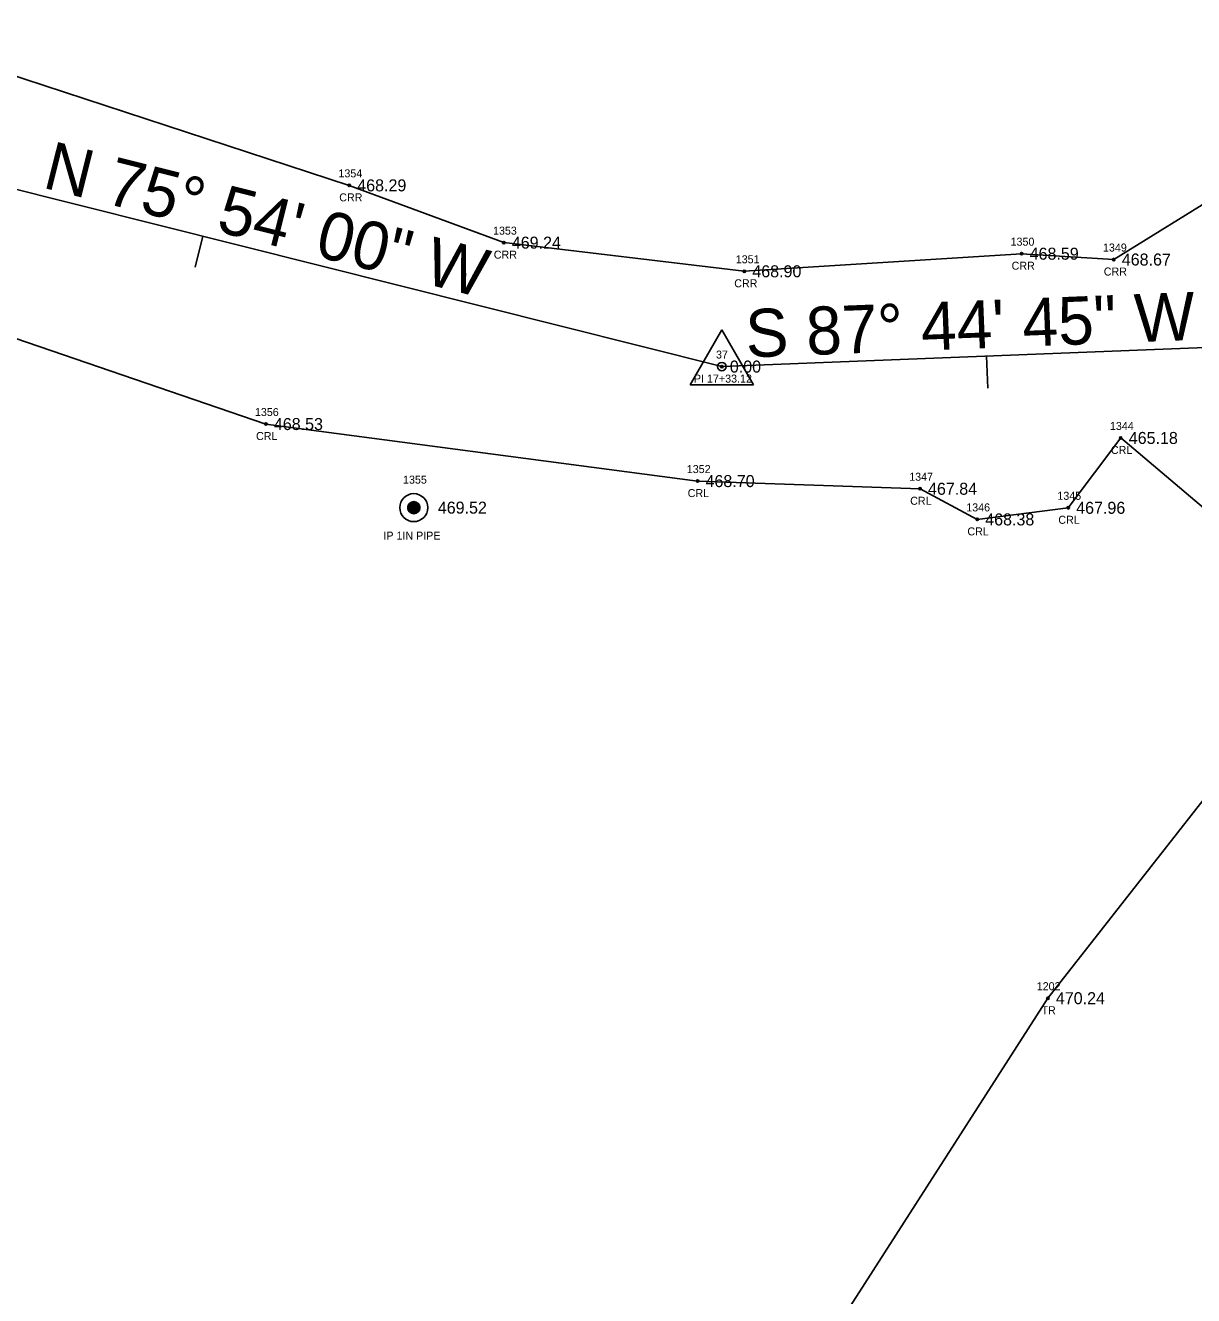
# Model space of a CAD drawing. Extents: x 1740701 to 1743138, y 748181 to 751839.
# Drawn here: x 1741406.9 to 1741552.9, y 750033.3 to 750192 of the extents above; entities that cross this region are included whole.
import ezdxf

# ---------------------------------------------------------------- set-up
doc = ezdxf.new("R2010")
doc.units = 0
for name, color, linetype in [('RD_EX_DV_Prop_txCode', 7, 'Continuous'), ('RD_EX_DV_PropPin', 7, 'Continuous'), ('RD_EX_H2O', 7, 'Continuous'), ('RD_EX_H2O_txCode', 7, 'Continuous'), ('RD_EX_TX_DV_Prop_ELEV', 7, 'Continuous'), ('RD_EX_TX_H2O_ELEV', 7, 'Continuous'), ('RD_EX_TX_VEG_ELEV', 7, 'Continuous'), ('RD_EX_VEG', 7, 'Continuous'), ('RD_EX_VEG_txCode', 7, 'Continuous'), ('RD_HC_Cl', 7, 'Continuous'), ('RD_HC_Data', 7, 'Continuous'), ('RD_HC_Data_Tic', 7, 'Continuous'), ('RD_HC_Survey_ELEV', 7, 'Continuous'), ('RD_HC_txCode', 7, 'Continuous'), ('RD_SMD_Locator', 7, 'Continuous')]:
    doc.layers.add(name, color=color, linetype=linetype)

msp = doc.modelspace()

# ---------------------------------------------------------------- linework, layer by layer
at = {"layer": 'RD_EX_DV_PropPin'}
for p, q in [((1741454.8, 750131.31), (1741454.8, 750132.17)), ((1741454.84, 750131.27), (1741454.84, 750132.21)), ((1741454.87, 750131.23), (1741454.87, 750132.26)), ((1741454.91, 750131.19), (1741454.91, 750132.29)), ((1741454.94, 750131.16), (1741454.94, 750132.32)), ((1741454.98, 750131.13), (1741454.98, 750132.35)), ((1741455.01, 750131.11), (1741455.01, 750132.38)), ((1741455.05, 750131.08), (1741455.05, 750132.4)), ((1741455.08, 750131.07), (1741455.08, 750132.42)), ((1741455.12, 750131.05), (1741455.12, 750132.43)), ((1741455.15, 750131.03), (1741455.15, 750132.45)), ((1741455.19, 750131.02), (1741455.19, 750132.46)), ((1741455.22, 750131.01), (1741455.22, 750132.47)), ((1741455.26, 750131), (1741455.26, 750132.48)), ((1741455.29, 750130.99), (1741455.29, 750132.49)), ((1741455.33, 750130.99), (1741455.33, 750132.49)), ((1741455.36, 750130.98), (1741455.36, 750132.5)), ((1741455.4, 750130.98), (1741455.4, 750132.5)), ((1741455.43, 750130.98), (1741455.43, 750132.5)), ((1741455.47, 750130.98), (1741455.47, 750132.5)), ((1741455.5, 750130.98), (1741455.5, 750132.5)), ((1741455.54, 750130.99), (1741455.54, 750132.49)), ((1741455.57, 750130.99), (1741455.57, 750132.49)), ((1741455.61, 750131), (1741455.61, 750132.48)), ((1741455.64, 750131.01), (1741455.64, 750132.47)), ((1741455.68, 750131.02), (1741455.68, 750132.46)), ((1741455.71, 750131.03), (1741455.71, 750132.45)), ((1741455.75, 750131.05), (1741455.75, 750132.43)), ((1741455.78, 750131.07), (1741455.78, 750132.42)), ((1741455.82, 750131.08), (1741455.82, 750132.4)), ((1741455.85, 750131.11), (1741455.85, 750132.38)), ((1741455.89, 750131.13), (1741455.89, 750132.35)), ((1741455.92, 750131.16), (1741455.92, 750132.32)), ((1741455.96, 750131.19), (1741455.96, 750132.29)), ((1741455.99, 750131.23), (1741455.99, 750132.26)), ((1741456.03, 750131.27), (1741456.03, 750132.21)), ((1741456.06, 750131.31), (1741456.06, 750132.17)), ((1741454.7, 750131.54), (1741454.7, 750131.94)), ((1741454.73, 750131.44), (1741454.73, 750132.04)), ((1741454.77, 750131.37), (1741454.77, 750132.11)), ((1741456.1, 750131.37), (1741456.1, 750132.11)), ((1741456.13, 750131.44), (1741456.13, 750132.04)), ((1741456.17, 750131.54), (1741456.17, 750131.94))]:
    msp.add_line(p, q, dxfattribs=at)
for radius in [1.75, 0.761]:
    msp.add_circle((1741455.43, 750131.74), radius, dxfattribs=at)
at = {"layer": 'RD_EX_H2O'}
for points in [[(1741586.49, 750141.56), (1741579.42, 750140.28), (1741574, 750158.88), (1741556.82, 750171.34), (1741542.92, 750162.75), (1741531.4, 750163.48), (1741496.74, 750161.28), (1741466.68, 750164.86), (1741447.36, 750172.02), (1741386.3, 750192.01)], [(1741577.19, 750059.87), (1741574.31, 750069.19), (1741563.25, 750082.19), (1741560.12, 750095.32), (1741559.96, 750109.5), (1741556.5, 750127.16), (1741554.14, 750131.7), (1741543.79, 750140.45), (1741537.22, 750131.72), (1741525.85, 750130.27), (1741518.7, 750134.1), (1741490.89, 750135.06), (1741436.94, 750142.19), (1741375.71, 750163.12), (1741339.37, 750188.79), (1741331.64, 750190.2), (1741328.64, 750186.11), (1741320.24, 750158.32), (1741318.27, 750146.83), (1741309.48, 750135.97), (1741304.66, 750127.91)]]:
    msp.add_lwpolyline(points, dxfattribs=at)
at = {"layer": 'RD_EX_VEG'}
msp.add_lwpolyline([(1741604.33, 750163.58), (1741599.49, 750153.1), (1741534.68, 750070.43), (1741507.94, 750028.75), (1741481.7, 749984.37), (1741451.24, 749945.89), (1741428.74, 749900.3), (1741397.03, 749864.21), (1741369.46, 749820.4), (1741343.59, 749775.26), (1741290.16, 749691.55)], dxfattribs=at)
at = {"layer": 'RD_HC_Cl'}
for p, q in [((1741493.93, 750149.37), (1741380.2, 750177.94)), ((1741557.27, 750151.87), (1741493.93, 750149.37))]:
    msp.add_line(p, q, dxfattribs=at)
msp.add_arc((1743076.32, 748855.91), 1908.9, 137.32219, 146.96645, dxfattribs=at)
at = {"layer": 'RD_HC_Data'}
for p, q in [((1741489.96, 750147.08), (1741493.93, 750153.96)), ((1741493.93, 750153.96), (1741497.9, 750147.08)), ((1741489.96, 750147.08), (1741497.9, 750147.08))]:
    msp.add_line(p, q, dxfattribs=at)
msp.add_circle((1741493.93, 750149.37), 0.529, dxfattribs=at)
at = {"layer": 'RD_HC_Data_Tic'}
for p, q in [((1741429.06, 750165.67), (1741428.09, 750161.79)), ((1741527.02, 750150.68), (1741527.18, 750146.68))]:
    msp.add_line(p, q, dxfattribs=at)
at = {"layer": 'RD_SMD_Locator'}
for centre in [(1741447.36, 750172.02), (1741466.68, 750164.86), (1741531.4, 750163.48), (1741542.92, 750162.75), (1741496.74, 750161.28), (1741493.93, 750149.37), (1741436.94, 750142.19), (1741543.79, 750140.45), (1741490.89, 750135.06), (1741518.7, 750134.1), (1741455.43, 750131.74), (1741537.22, 750131.72), (1741525.85, 750130.27), (1741534.68, 750070.43)]:
    msp.add_circle(centre, 0.15, dxfattribs=at)

# ---------------------------------------------------------------- texts
at = {"layer": 'RD_EX_DV_Prop_txCode'}
for s, p in [('1355', (1741454.08, 750134.74)), ('IP 1IN PIPE', (1741451.63, 750127.74))]:
    msp.add_text(s, height=1, dxfattribs=at).set_placement(p)
at = {"layer": 'RD_EX_H2O_txCode'}
for s, p in [('1354', (1741446.01, 750173.02)), ('CRR', (1741446.11, 750170.02)), ('1353', (1741465.33, 750165.86)), ('1350', (1741530.02, 750164.48)), ('1349', (1741541.57, 750163.75)), ('CRR', (1741465.43, 750162.86)), ('1351', (1741495.67, 750162.28)), ('CRR', (1741530.15, 750161.48)), ('CRR', (1741541.67, 750160.75)), ('CRR', (1741495.48, 750159.28)), ('1356', (1741435.57, 750143.19)), ('1344', (1741542.44, 750141.45)), ('CRL', (1741435.71, 750140.19)), ('CRL', (1741542.56, 750138.45)), ('1352', (1741489.55, 750136.06)), ('1347', (1741517.35, 750135.1)), ('CRL', (1741489.66, 750133.06)), ('CRL', (1741517.47, 750132.1)), ('1346', (1741524.48, 750131.27)), ('1345', (1741535.87, 750132.72)), ('CRL', (1741535.99, 750129.72)), ('CRL', (1741524.62, 750128.27))]:
    msp.add_text(s, height=1, dxfattribs=at).set_placement(p)
at = {"layer": 'RD_EX_TX_DV_Prop_ELEV'}
msp.add_text('469.52', height=1.5, dxfattribs=at).set_placement((1741458.43, 750130.99))
at = {"layer": 'RD_EX_TX_H2O_ELEV'}
for s, p in [('468.29', (1741448.36, 750171.27)), ('469.24', (1741467.68, 750164.11)), ('468.59', (1741532.4, 750162.73)), ('468.67', (1741543.92, 750162)), ('468.90', (1741497.74, 750160.53)), ('468.53', (1741437.94, 750141.44)), ('465.18', (1741544.79, 750139.7)), ('468.70', (1741491.89, 750134.31)), ('467.84', (1741519.7, 750133.35)), ('467.96', (1741538.22, 750130.97)), ('468.38', (1741526.85, 750129.52))]:
    msp.add_text(s, height=1.5, dxfattribs=at).set_placement(p)
at = {"layer": 'RD_EX_TX_VEG_ELEV'}
msp.add_text('470.24', height=1.5, dxfattribs=at).set_placement((1741535.68, 750069.68))
at = {"layer": 'RD_EX_VEG_txCode'}
for s, p in [('1202', (1741533.29, 750071.43)), ('TR', (1741533.88, 750068.43))]:
    msp.add_text(s, height=1, dxfattribs=at).set_placement(p)
at = {"layer": 'RD_HC_Data'}
for s, rotation, p in [('N 75%%d 54\' 00" W', 345.8999, (1741408.87, 750171.77)), ('S 87%%d 44\' 45" W', 2.2541, (1741497, 750150.5))]:
    msp.add_text(s, height=6, rotation=rotation, dxfattribs=at).set_placement(p)
at = {"layer": 'RD_HC_Survey_ELEV'}
msp.add_text('0.00', height=1.5, dxfattribs=at).set_placement((1741494.93, 750148.62))
at = {"layer": 'RD_HC_txCode'}
for s, p in [('37', (1741493.2, 750150.37)), ('PI 17+33.12', (1741490.44, 750147.37))]:
    msp.add_text(s, height=1, dxfattribs=at).set_placement(p)

doc.saveas('drawing.dxf')
